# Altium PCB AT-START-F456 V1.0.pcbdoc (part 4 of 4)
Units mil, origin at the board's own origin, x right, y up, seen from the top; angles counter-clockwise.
Board outline 10942.5 x 3554 mil, 2 copper layers (Top Layer, Bottom Layer); 156 components, 201 nets, 759 pads, 796 vias.
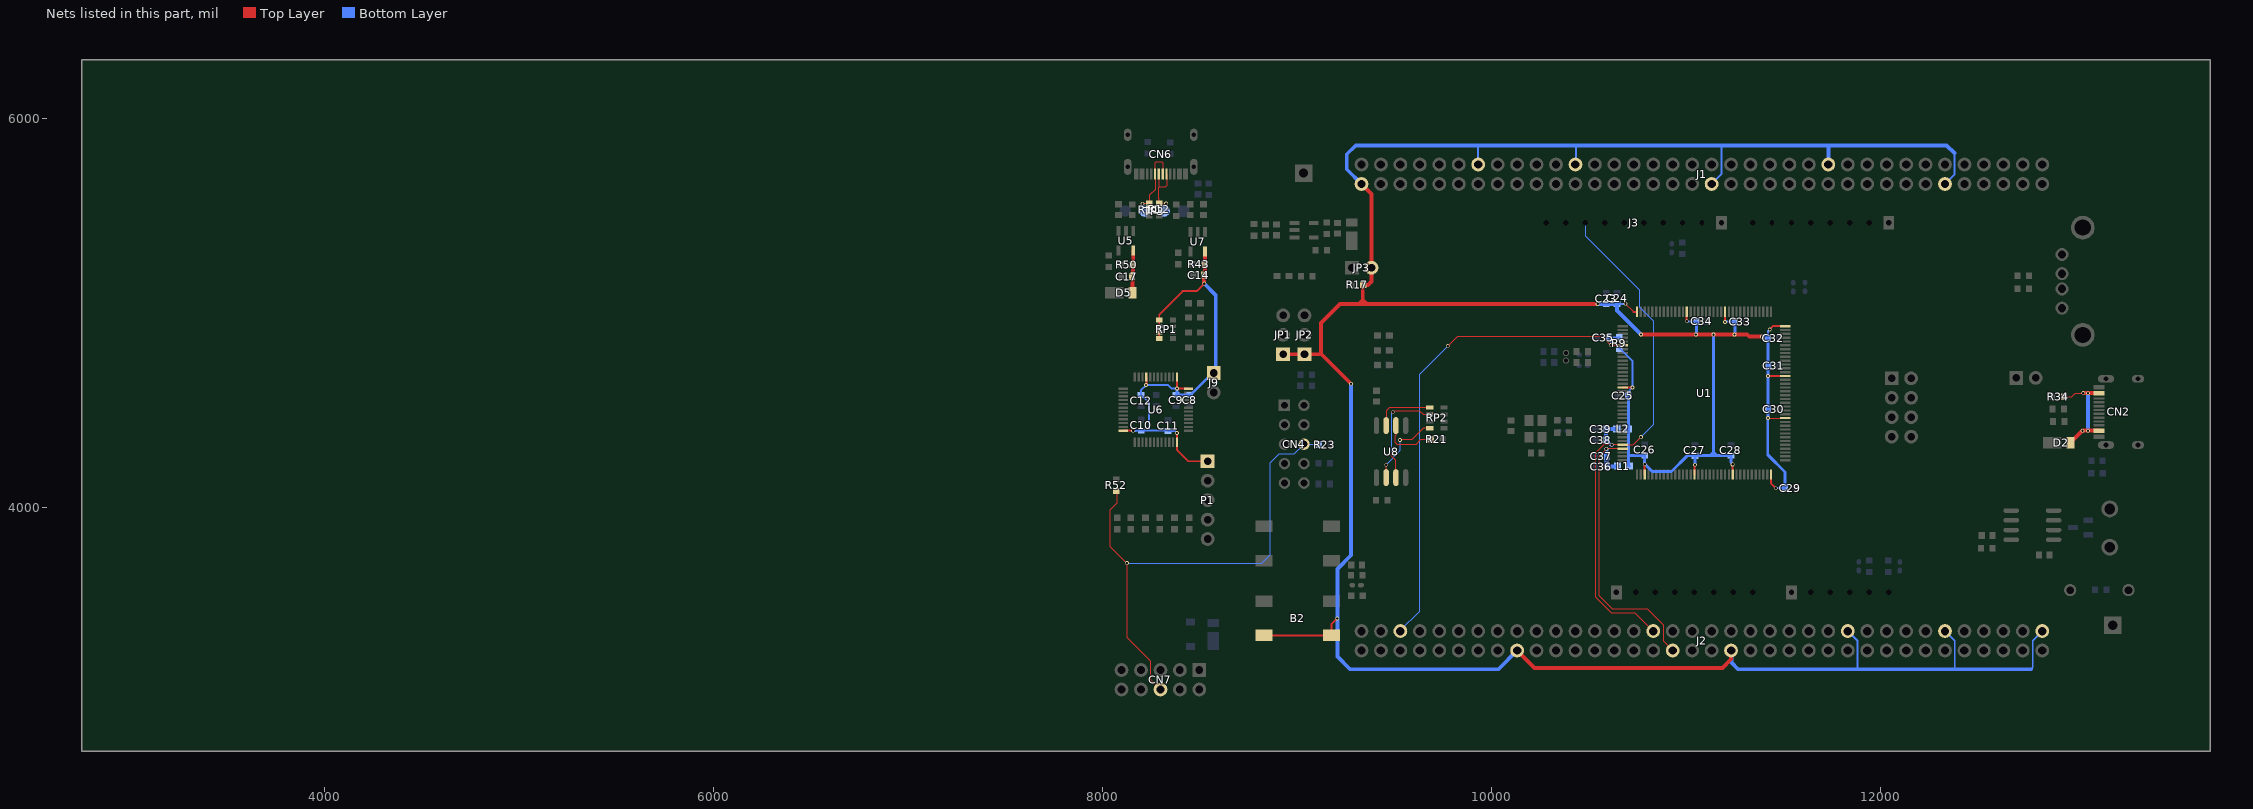
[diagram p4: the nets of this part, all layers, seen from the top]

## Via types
v1: diameter 19.7, hole 11.8, Top Layer to Bottom Layer, 419 vias
v2: diameter 19.68, hole 11.81, Top Layer to Bottom Layer, 364 vias
v3: diameter 31.5, hole 19.68, Top Layer to Bottom Layer, 12 vias
v4: diameter 27.56, hole 19.68, Top Layer to Bottom Layer, 1 vias

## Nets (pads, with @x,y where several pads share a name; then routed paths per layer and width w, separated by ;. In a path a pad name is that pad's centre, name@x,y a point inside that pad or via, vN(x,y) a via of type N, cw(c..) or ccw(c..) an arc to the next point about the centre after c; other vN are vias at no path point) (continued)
QSPI1_IO1: RP2.8 U8.2 | length 401.8
  Top Layer w5.98: U8.2@9456.16,4155.92 v2(9456.18,4222.41)
  Top Layer w6: v2(9526.59,4349.49) 9586.44,4349.49 9646.8,4409.85 RP2.8@9680.35,4409.85 ccw(c9680.11,4409.6) RP2.8@9680.11,4409.95
  Bottom Layer w6: v2(9456.18,4222.41) 9456.18,4223.22 9526.59,4293.63 v2(9526.59,4349.49)
QSPI1_IO2: RP2.6 U8.3 | length 552.2
  Top Layer w5.98: v2(9482.61,4281.14) 9482.61,4267.58 9506.16,4244.03 U8.3@9506.16,4155.92
  Top Layer w6: v2(9489.97,4492.3) 9498.29,4500.61 9625.57,4500.61 9645.47,4480.72 RP2.6@9680.35,4480.72
  Bottom Layer w5.98: v2(9482.61,4281.14) 9481.57,4282.18 9481.57,4483.9 v2(9489.97,4492.3)
QSPI1_IO3: RP2.5 U8.7 | length 307.3
  Top Layer w6: U8.7@9455.57,4424.23 ccw(c9456.18,4424.23) U8.7@9456.16,4423.64 ; U8.7@9455.56,4424.28 9455.56,4498.6 9473.1,4516.15 RP2.5@9680.35,4516.15
QSPI1_SCK: R21.2 U8.6 | length 287.1
  Top Layer w6: U8.6@9506.16,4423.64 9506.16,4374.87 9499.57,4368.29 9499.57,4340.61 9511.57,4328.61 9609.57,4328.61 9634.8,4353.85 R21.2@9685.52,4353.85
SWO: CN4.6 CN7.6 R23.1 R52.2 | length 2661.3
  Top Layer w6: 8070.23,4023.63 8035.17,3988.57 8035.17,3804.01 v2(8122.8,3716.38) 8124.77,3714.41 8124.77,3332.21 8245.21,3211.77 8245.21,3116.85 CN7.6@8295.43,3066.63 ; 8070.26,4023.68 R52.2@8070.26,4081.58
  Bottom Layer w6: v2(8122.8,3716.38) 8124.56,3714.61 8815.89,3714.61 8860.26,3758.98 8860.26,4231.98 8906.26,4277.98 8984.36,4277.98 9034.56,4328.18 9112.76,4328.18 R23.1@9112.76,4325.98
USBM: CN6.A7 CN6.B7 R12.1 TP3.2 | length 334.9
  Top Layer w6: CN6.A7@8287.41,5717.9 8287.41,5649.64 ; v2(8324.77,5565.01) 8324.24,5564.48 R12.1@8290.08,5564.48 8290.08,5586.36 8287.41,5589.03 8287.41,5649.64 ; CN6.B7@8326.71,5717.9 8326.71,5657.74 8318.61,5649.64 8287.41,5649.64
  Bottom Layer w6: TP3.2@8314.58,5526.61 8324.77,5536.8 v2(8324.77,5565.01)
USBP: CN6.A6 CN6.B6 R11.1 TP3.3 | length 398.8
  Top Layer w6: v2(8203.57,5563.81) 8203.69,5563.69 R11.1@8238.07,5563.69 8238.07,5607.32 8267.71,5636.95 CN6.B6@8267.71,5717.9 8267.71,5774.07 8272.74,5779.1 8302.29,5779.1 8307.01,5774.39 CN6.A6@8307.01,5717.9
  Bottom Layer w6: v2(8203.57,5563.81) 8203.57,5537.62 TP3.3@8214.58,5526.61
VBAT: C35.1 J2.6 R9.1 U1.6 | length 2722.4
  Top Layer w6: v2(9772.21,4831.97) 9821.36,4881.18 10566.96,4881.18 v2(10611.21,4836.97) 10612.06,4836.08 U1.6@10671.86,4836.08
  Top Layer w10: v2(10611.21,4836.97) U1.6@10671.86,4836.08
  Bottom Layer w6: J2.6@9529.17,3367.08 9529.16,3370.98 9628.26,3470.08 9628.26,4687.98 v2(9772.21,4831.97) ; C35.1@10598.77,4875.97 10654.76,4875.98 R9.1@10655.26,4875.48
  Bottom Layer w10: v2(10611.21,4836.97) 10611.16,4863.48 10598.66,4875.98 R9.1@10655.16,4875.48
VBUS: CN2.A4B9 CN2.B4A9 D2.2 R34.2 | length 552.1
  Top Layer w5.98: 12981.88,4572.61 12999.58,4590.32 v1(13039.74,4590.32)
  Top Layer w6: R34.2@12941.23,4572.61 12981.88,4572.61
  Top Layer w20: D2.2@12974.39,4335.82 v1(13035.89,4397.32) v1(13063.79,4397.32) CN2.A4B9@13120.94,4397.32 ; v1(13039.74,4590.32) CN2.B4A9@13120.94,4590.32
  Bottom Layer w20: v1(13063.79,4397.32) v1(13063.79,4589.97) v1@13064.04,4590.22
VCC: C8.2 C9.2 C10.2 C11.2 C12.2 C14.2 J9.1 P1.1 R43.1 RP1.1 RP1.2 RP1.3 RP1.4 U6.1 U6.9 U6.24 U6.36 U6.48 U7.5 | length 2489.8
  Top Layer w10: U6.24@8104.56,4397.08 8154.68,4397.08 v2(8155.18,4396.59) ; v2(8221.57,4631.81) 8222.69,4632.94 U6.9@8222.69,4672.63 ; RP1.4@8289.33,4870.97 RP1.3@8289.33,4902.46 RP1.2@8289.33,4933.96 RP1.1@8289.33,4965.45 8289.33,4994.38 8409.97,5115.01 8482.37,5115.01 v2(8520.77,5153.41) ; v2(8379.97,4385.01) 8380.17,4384.81 U6.36@8380.17,4337.98 8380.16,4298.64 8438.61,4240.18 P1.1@8538.16,4240.18 ; U6.1@8380.16,4672.68 8380.16,4632.38 8380.46,4632.08 v2(8380.46,4613.78) 8400.16,4613.78 8400.36,4613.58 U6.48@8439.26,4613.58
  Top Layer w20: v2(8520.77,5153.41) 8519.37,5154.82 C14.2@8519.37,5197.16 8524.34,5202.13 U7.5@8524.34,5318.39
  Bottom Layer w6: C10.2@8196.77,4398.65 C10.2@8198.74,4398.65
  Bottom Layer w10: v2(8155.18,4396.59) 8170.98,4396.59 8173.05,4398.65 C10.2@8196.77,4398.65 ; C10.2@8198.74,4398.65 8235.87,4398.65 ; v2(8379.97,4385.01) 8369.13,4395.85 C11.2@8335.17,4395.85 8332.01,4399.01 8299.97,4399.01 8299.61,4398.65 8235.87,4398.65 ; v2(8380.46,4613.78) 8353.6,4613.78 8335.57,4631.81 v2(8221.57,4631.81) 8196.37,4606.61 C12.2@8196.37,4579.77 8198.34,4579.77 8235.57,4542.54 8235.57,4398.95 8235.87,4398.65
  Bottom Layer w15: v2(8380.46,4613.78) 8380.46,4584.26 C9.2@8376.37,4580.17 8445.57,4580.17 C8.2@8446.37,4580.97 8450.73,4580.97 8563.33,4693.58 J9.1@8569.46,4693.58
  Bottom Layer w20: v2(8520.77,5153.41) 8579.57,5094.61 8579.57,4703.69 J9.1@8569.46,4693.58
VCC3.5V: C17.2 D5.2 R50.1 U5.5 | length 217
  Top Layer w20: D5.2@8152.36,5107.05 U5.5@8155.56,5324.05
VDD: B2.1 B2.3 C23.1 C24.1 C25.1 C26.1 C27.1 C28.1 C29.1 C30.1 C31.1 C32.1 C33.1 C34.1 J1.12 J1.23 J1.36 J1.49 J1.59 J1.72 J2.17 J2.39 J2.52 J2.62 J2.72 JP1.1 JP2.1 JP3.2 L1.1 L2.1 R9.2 R17.2 U1.17 U1.39 U1.52 U1.62 U1.72 U1.84 U1.95 U1.108 U1.121 U1.131 U1.144 | length 18180.8
  Top Layer w6: v2@10686.26,5049.98 10727.86,5008.28 ; v2(11001.21,4959.97) 11001.16,5007.88 U1.131@11001.66,5008.28 ; v2@11198.26,4955.98 11198.26,5007.98 U1.121@11198.46,5008.28 ; v2(11237.21,4223.97) 11237.86,4223.28 U1.62@11237.86,4171.68 ; v2(11419.26,4462.98) 11420.26,4461.98 11508.36,4461.98 U1.84@11508.56,4461.98
  Top Layer w10: B2.3@8828.03,3344.39 B2.1@9174.49,3344.39 9174.46,3402.18 v2@9204.26,3431.98 ; U1.17@10671.86,4619.52 v2(10722.29,4619.56) ; 10727.86,5008.28 U1.144@10745.68,5008.31 ; U1.39@10785.06,4171.68 v2(10785.09,4224.97) ; v2(11001.21,4959.97) U1.131@11001.66,5008.28 ; U1.52@11040.96,4171.68 11040.96,4218.78 v2@11044.26,4221.98 ; v2@11198.26,4955.98 U1.121@11198.46,5008.28 ; v2(11237.21,4223.97) U1.62@11237.86,4171.68 ; v2(11419.26,4678.58) U1.95@11508.48,4678.57 ; v2(11428.26,4917.98) 11444.76,4934.48 U1.108@11508.48,4934.48 ; U1.72@11434.66,4171.68 11434.66,4125.48 v2@11459.26,4100.98 ; U1.84@11508.36,4461.98 U1.84@11508.46,4462.08
  Top Layer w20: JP1.1@8926.26,4789.98 9036.26,4789.98 9121.56,4789.98 ; v2(9275.08,4638.41) 9123.56,4789.98 9121.56,4789.98 ; J1.72@9329.18,5665.65 9380.21,5614.62 JP3.2@9380.21,5234.97 ; JP3.2@9380.21,5234.97 9380.16,5164.98 9362.26,5146.98 9335.76,5146.98 9335.86,5070.28 ; J2.17@10129.17,3267.08 10218.28,3177.97 11185.21,3177.97 11229.18,3221.93 J2.39@11229.17,3267.08 ; v2@10543.26,5048.98 9357.26,5048.98 ; v2(10765.65,4891.76) 10765.87,4891.98 v2@11048.26,4891.98 ; v2(11048.21,4891.97) v2(11247.21,4891.97) 11312.67,4891.97 11323.77,4880.87 v1(11387.81,4880.87) ; 9121.56,4789.98 9121.56,4951.28 9219.26,5048.98 9315.36,5048.98 ; 9315.36,5048.98 9335.86,5070.28 ; 9315.36,5048.98 9357.26,5048.98 ; 9335.86,5070.28 9357.26,5048.98
  Bottom Layer w6: v2(11001.21,4959.97) v2@11002.16,4958.98 ; C32.1@11418.02,4872.73 C32.1@11418.02,4879.87 ; v2@11459.26,4100.98 v2@11460.26,4101.98
  Bottom Layer w10: J1.59@9929.18,5765.65 9929.18,5862.18 9931.37,5864.38 ; J1.49@10429.18,5765.65 10432.2,5768.67 10432.2,5864.38 ; C24.1@10643.21,5049.41 10685.65,5049.41 v2(10686.21,5049.97) ; R9.2@10655.16,4820.48 10658.06,4820.48 10722.26,4756.28 v2(10722.29,4619.56) 10700.76,4597.98 ; v2@11001.16,4958.98 11002.16,4958.98 C34.1@11050.76,4958.98 ; J1.36@11129.18,5665.65 11179.27,5715.74 11179.27,5864.38 ; v2@11198.26,4955.98 11200.16,4957.98 C33.1@11249.65,4957.97 ; C32.1@11419.02,4880.87 11419.02,4908.74 v2(11428.26,4917.98) ; C30.1@11420.01,4508.61 11422.36,4510.97 C30.1@11431.65,4510.97 ; v2@11459.26,4100.98 11460.16,4101.98 11460.26,4101.98 C29.1@11506.65,4101.97 ; J2.52@11829.17,3367.08 11879.21,3317.04 11879.21,3170.98 ; J2.62@12329.17,3367.08 12379.21,3317.04 12379.21,3170.98 ; J1.12@12329.18,5665.65 12377.21,5713.68 12377.21,5823.97 ; 12771.26,3170.98 12780.26,3179.98 12780.26,3318.08 J2.72@12829.17,3367.08
  Bottom Layer w15: 10700.76,4597.98 10701.87,4596.87 L2.1@10701.88,4406.61 10701.87,4270.79 10701.56,4270.48 ; L1.1@10705.57,4214.98 10701.56,4218.98 10701.56,4270.48 ; C27.1@11043.26,4268.48 11003.66,4268.48 10922.88,4187.61 10823.59,4187.61 10785.06,4226.01 10785.26,4270.48 10701.56,4270.48 ; C27.1@11043.26,4269.48 11122.36,4269.48 ; v2@11044.26,4221.98 C27.1@11044.26,4267.48 ; v2@11048.26,4891.98 11050.76,4891.98 C34.1@11050.76,4958.98 ; 11138.66,4285.98 11122.36,4269.48 ; v2(11138.7,4890.97) 11138.7,4285.98 11155.2,4269.48 ; v2@11237.26,4223.98 11228.26,4232.98 11228.26,4269.48 11155.2,4269.48 ; v2(11247.21,4891.97) 11249.66,4894.48 C33.1@11249.65,4957.97 ; v2@11418.01,4454.73 11418.01,4273.17 11420.01,4271.17 11506.65,4184.53 C29.1@11506.65,4101.97 ; v2@11420.01,4462.77 C30.1@11420.01,4508.61 C32.1@11420.01,4872.61 ; 11122.36,4269.48 11155.2,4269.48
  Bottom Layer w20: v2(9275.08,4638.41) 9275.08,3756.83 9205.26,3687.01 9205.26,3235.98 9270.26,3170.98 10033.06,3170.98 J2.17@10129.17,3267.08 ; J1.72@9329.16,5665.68 9253.46,5741.38 9253.46,5818.28 9299.56,5864.38 9931.37,5864.38 10432.2,5864.38 11179.27,5864.38 11729.18,5864.38 ; v2(10543.21,5048.97) 10587.57,5048.97 10642.77,5048.97 C24.1@10643.21,5049.41 10643.21,5014.2 v2(10765.65,4891.76) ; J2.39@11229.17,3267.08 11231.21,3265.04 11231.21,3204.97 11265.2,3170.98 11879.21,3170.98 12379.21,3170.98 12771.26,3170.98 ; v1(11387.81,4880.87) C32.1@11418.01,4880.87 ; J1.23@11729.18,5765.65 11729.18,5864.38 ; 12377.26,5823.98 12336.76,5864.38 11729.18,5864.38
  other v2: 9204.21,3431.97 11459.21,4100.97 11044.21,4221.97 11198.21,4955.97
VDDA: C36.1 C37.1 J2.33 L1.2 U1.33 | length 1590.7
  Top Layer w6: U1.33@10671.86,4304.56 10588.86,4304.58 10548.16,4263.88 10548.16,3552.03 10619.2,3480.98 10799.46,3480.98 10880.26,3400.18 10880.26,3316.08 J2.33@10929.17,3267.08
  Bottom Layer w6: v2@10588.26,4303.98 10588.66,4303.48 C37.1@10588.66,4264.98 ; L1.2@10642.86,4212.98 L1.2@10644.94,4214.98
  Bottom Layer w20: v2@10588.26,4303.98 10588.66,4264.98 10588.66,4212.98 L1.2@10642.86,4212.98 ; L1.2@10642.96,4212.98 L1.2@10644.96,4214.98
  other v2: 10588.21,4303.97
VREF+: C38.1 C39.1 J2.32 J3.8 L2.2 U1.32 | length 2915.4
  Top Layer w6: v2(10616.21,4324.97) 10671.16,4324.98 U1.32@10671.86,4324.24 ; v2@10765.66,4363.98 10725.86,4324.18 U1.32@10671.86,4324.24 ; J2.32@10829.17,3367.08 10734.26,3461.98 10612.2,3461.98 10531.56,3542.63 10531.56,4281.28 10574.46,4324.18 U1.32@10671.86,4324.24
  Bottom Layer w6: J3.8@10479.86,5465.98 10479.86,5400.33 10758.26,5121.93 10758.26,5033.65 10828.93,4962.97 10828.93,4427.25 v2@10765.66,4363.98 ; C39.1@10586.77,4404.97 10586.76,4348.98 C38.1@10587.13,4348.61 ; L2.2@10639.53,4404.98 L2.2@10641.25,4406.61
  Bottom Layer w20: v2(10616.21,4324.97) 10610.76,4324.98 C38.1@10587.13,4348.61 10587.12,4404.62 C39.1@10586.77,4404.97 L2.2@10639.53,4404.98 ; L2.2@10639.63,4404.98 L2.2@10641.27,4406.61
  other v2: 10765.63,4364
pads on no net: CN2.A8 CN2.B8 CN6.A8 CN6.B8 J4.1 J4.8 U6.2 U6.3 U6.4 U6.5 U6.6 U6.14 U6.15 U6.16 U6.17 U6.18 U6.21 U6.22 U6.29 U6.38 U6.41 U6.42 U6.43 U6.45 U6.46

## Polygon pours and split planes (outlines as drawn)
GND on Top Layer (solid, remove dead copper, pour order 0): 7929.57,6050.61 13439.57,6050.61 13439.57,3000.61 7929.57,3000.61
GND on Bottom Layer (solid, remove dead copper, pour order 2): 7904.5,6054 13442.5,6054 13442.5,3000 7904.5,3000

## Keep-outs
Top Layer:
  region: 8093.57,6044.61 8503.57,6044.61 8503.57,5692.61 8093.57,5692.61
  region: 11000.57,5092.61 11028.57,5092.61 11028.57,5089.61 11000.57,5089.61
  region: 8427.33,4456.25 8427.33,4435.51 8454.37,4435.51 8454.37,4456.25 8427.4,4456.25
  region: 9705.37,4533.67 9727.83,4533.67 9727.83,4528.15 9705.37,4528.15
Board Outline Layer:
  circle w1: c12139.81,4865.97 r62.99
  circle w10: c12139.81,4865.97 r62.99
  circle w1: c10139.81,5465.96 r62.99
  circle w10: c10139.81,5465.96 r62.99
  circle w1: c10089.81,3565.97 r62.99
  circle w10: c10089.81,3565.97 r62.99
  circle w1: c8818.39,5874.63 r62.99
  circle w10: c8818.39,5874.63 r62.99
  circle w1: c8818.39,3158.09 r62.99
  circle w10: c8818.39,3158.09 r62.99
  circle w1: c13109.73,3158.09 r62.99
  circle w10: c13109.73,3158.09 r62.99
  circle w1: c13109.73,5874.63 r62.99
  circle w10: c13109.73,5874.63 r62.99
  region: 13010.04,4104.05 13438.4,4104.05 13438.4,3683.8 13010.04,3683.8
  lines w8: 8582.96,6032.21 cw(c8582.96,5953.47) 8661.7,5953.47 8661.7,5631.63 8701.21,5631.63 8701.21,5953.46 cw(c8779.95,5953.46) 8779.95,6032.2 ; 8583.39,3000.61 ccw(c8583.39,3079.35) 8662.13,3079.35 8662.16,3079.38 8662.16,3518.58 8700.96,3518.58 8700.96,3079.38 8700.96,3079.35 ccw(c8779.7,3079.35) 8779.7,3000.61 ; 8661.66,5546.58 8661.66,5553.58 8701.26,5553.58 8701.26,5546.58 8701.22,5546.58 8701.22,5224.75 8701.22,4903.97 ; 8661.7,5546.59 8661.7,5224.75 8661.7,4904.49 ; 8661.7,4904.49 8662.57,4903.61 ; 8661.7,4904.49 ccw(c8662.57,4904.49) 8662.57,4903.61 ; 8662.57,4903.61 8700.86,4903.61 ; 8700.86,4903.61 8701.22,4903.97 ; 8700.86,4903.61 ccw(c8700.86,4903.97) 8701.22,4903.97 ; 8661.57,3606.61 8661.57,3698.61 8701.57,3698.61 8701.57,3606.61 8661.57,3606.61 ; 8661.57,3810.61 8661.57,4809.61 8661.57,4825.61 8680.57,4825.61 8700.57,4825.61 8700.57,3825.61 8700.57,3810.61 8699.57,3810.61 8661.57,3810.61
  lines w10: 7929.57,3079.35 ccw(c8008.31,3079.35) 8008.31,3000.61 13362.64,3000.61 ccw(c13362.64,3079.35) 13441.38,3079.35 13441.38,5953.37 ccw(c13362.64,5953.37) 13362.64,6032.11 8008.31,6032.11 ccw(c8008.31,5953.37) 7929.57,5953.37 7929.57,3079.35

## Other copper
Top Layer:
  drawing of 902 lines, arcs and shapes, not listed
Bottom Layer:
  drawing of 563 lines, arcs and shapes, not listed

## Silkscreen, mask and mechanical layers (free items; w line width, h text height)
Top Silkscreen Layer:
  region: 12061.06,5334.85 12023.06,5334.85 12043.06,5354.85 12063.06,5334.85
  region: 11922.7,5352.85 11960.7,5352.85 11940.7,5332.85 11920.7,5352.85
  lines w6: 8141.98,3304.61 8141.98,3603.61 ; 8238.38,3304.61 8238.38,3603.61 ; 8334.77,3303.61 8334.77,3603.61 ; 8431.17,3309.61 8431.17,3603.61
  lines w8: 8243,3218.63 8243,3258.63 8343,3258.63 8343,3217.63 ; 8533.55,3272.63 8496.55,3235.63 8457.55,3274.63 8533.55,3274.63 ; 8842.11,4558.1 8875.56,4528.18 8841.33,4499.39 8841.33,4557.7 8842.9,4557.31 ; 8881.91,4376.46 8859.05,4376.46 8859.05,4277.18 8882.06,4277.18 8882.06,4278.37
  lines w10: 10652.7,5212.76 12068.4,5212.76 ; 10942.92,3858.17 11395.93,3858.17 ; 11541.16,3858.17 12101.16,3858.17
  text "143" at 9294.03,5925.4 h53.08
  text "133" at 9778.67,5925.4 h53.08
  text "123" at 10283.4,5925.34 h53.08
  text "113" at 10800.72,5925.42 h53.08
  text "103" at 11286.94,5925.43 h53.08
  text "93" at 11797.25,5925.41 h53.08
  text "83" at 12303.16,5925.43 h53.08
  text "73" at 12798.04,5925.41 h53.08
  text "D8" at 12614.84,5826.64 h53.08 r45
  text "B12" at 12814.13,5827.4 h53.08 r45
  text "E0" at 9430.12,5824.52 h53.08 r45
  text "D7" at 10318.9,5825.28 h53.08 r45
  text "D12" at 12415.09,5824.62 h53.08 r45
  text "D10" at 12514.89,5825.31 h53.08 r45
  text "B14" at 12714.99,5825.34 h53.08 r45
  text "B8" at 9526.51,5823.55 h53.08 r45
  text "B3" at 9826.63,5823.87 h53.08 r45
  text "D1" at 10725.32,5823.89 h53.08 r45
  text "A14" at 11016.9,5823.66 h53.08 r45
  text "A13" at 11214.65,5823.89 h53.08 r45
  text "A11*" at 11319.48,5823.92 h53.08 r45
  text "A9" at 11426.06,5823.63 h53.08 r45
  text "D14" at 12219.86,5823.66 h53.08 r45
  text "B5" at 9727.99,5823.17 h53.08 r45
  text "D5" at 10530.89,5822.21 h53.08 r45
  text "D3" at 10626.84,5822.42 h53.08 r45
  text "B7" at 9625.2,5820.13 h53.08 r45
  text "G10" at 10218.23,5820.36 h53.08 r45
  text "G8" at 11820.07,5819.93 h53.08 r45
  text "G12" at 10118.32,5818.91 h53.08 r45
  text "GND" at 11114.44,5819.33 h53.08 r45
  text "G2" at 12119.89,5819.18 h53.08 r45
  text "GND" at 9334.9,5817.96 h53.08 r45
  text "C7" at 11625.79,5817.66 h53.08 r45
  text "G6" at 11922.73,5818.3 h53.08 r45
  text "C12" at 10818.19,5816.54 h53.08 r45
  text "C9" at 11519.64,5817.36 h53.08 r45
  text "G4" at 12017.33,5817.43 h53.08 r45
  text "GND" at 12312.34,5817.24 h53.08 r45
  text "G14" at 10017.34,5816.49 h53.08 r45
  text "VDD" at 10418.16,5815.77 h53.08 r45
  text "C10" at 10920.36,5815.82 h53.08 r45
  text "VDD" at 11710.07,5815.74 h53.08 r45
  text "VDD" at 9913.84,5812.5 h53.08 r45
  text "GND" at 8977.64,5808.6 h61.93
  text "B6" at 9742.77,5537.36 h53.08 r45
  text "B9" at 9540.12,5533.83 h53.08 r45
  text "E1" at 9435.76,5530.95 h53.08 r45
  text "B4" at 9835.99,5531.15 h53.08 r45
  text "D6" at 10432.23,5530.95 h53.08 r45
  text "G11" at 10230.83,5527.56 h53.08 r45
  text "D4" at 10637.55,5524.86 h53.08 r45
  text "G13" at 10109.58,5524.31 h53.08 r30
  text "G9" at 10324.42,5524.4 h53.08 r45
  text "D0" at 10838.83,5524.06 h53.08 r45
  text "G5" at 12031.09,5523.75 h53.08 r45
  text "G3" at 12133.79,5523.58 h53.08 r45
  text "D2" at 10739.23,5522.71 h53.08 r45
  text "H2" at 11232.67,5523.43 h53.08 r45
  text "C6" at 11737.72,5522.99 h53.08 r45
  text "G7" at 11932.92,5522.76 h53.08 r45
  text "A8" at 11533.03,5521.69 h53.08 r45
  text "C8" at 11633,5522.25 h53.08 r45
  text "C11" at 10934.3,5519.65 h53.08 r45
  text "A10" at 11429.72,5519.73 h53.08 r45
  text "G15" at 9928.83,5517.95 h53.08 r45
  text "D11" at 12532.33,5516.61 h53.08 r45
  text "A15" at 11025.3,5515.46 h53.08 r45
  text "D15" at 12226.07,5515 h53.08 r45
  text "D9" at 12634.99,5513.64 h53.08 r45
  text "VDD" at 9317.08,5512.52 h53.08 r45
  text "GND" at 11820.45,5513.47 h53.08 r45
  text "GND" at 10021.29,5511.87 h53.08 r45
  text "GND" at 10526.54,5511.97 h53.08 r45
  text "A12*" at 11322.84,5511.95 h53.08 r45
  text "B15" at 12734.91,5511.09 h53.08 r45
  text "D13" at 12427.78,5509.01 h53.08 r45
  text "B13" at 12832.59,5509.41 h53.08 r45
  text "VDD" at 11121.07,5507.7 h53.08 r45
  text "VDD" at 12323.24,5503.68 h53.08 r45
  text "BOOT0" at 9597.79,5485.43 h44.24 r45
  text "HOST" at 13163.09,5483.02 h80
  text "4" at 11676.82,5362.91 h69.7 r90
  text "8" at 11216.74,5361.97 h69.7 r90
  text "7" at 11379.82,5361.91 h69.7 r90
  text "2" at 11873.82,5361.91 h69.7 r90
  text "13" at 10719.33,5322.2 h70.78 r90
  text "12" at 10819.33,5322.2 h70.78 r90
  text "#6" at 11476.41,5316.14 h70.78 r90
  text "#5" at 11577.41,5316.14 h70.78 r90
  text "#9" at 11120.33,5315.2 h70.78 r90
  text "#3" at 11776.41,5315.14 h70.78 r90
  text "#11" at 10920.62,5295.36 h70.78 r90
  text "#10" at 11019.98,5289.01 h70.78 r90
  text "GND" at 10621.15,5268.8 h70.78 r90
  text "SCL" at 10315.33,5266.66 h70.78 r90
  text "SDA" at 10415.33,5266.66 h70.78 r90
  text "RX 0" at 12081.98,5235.78 h70.78 r90
  text "TX 1" at 11978.75,5234.59 h70.78 r90
  text "DIGITAL(#=PWM)" at 11091.16,5233.28 h61.93
  text "AREF" at 10519.33,5230.13 h70.78 r90
  text "IDD" at 9470.36,5181.95 h88.47
  text "LD:" at 8563.5,5173.13 h72 r270
  text "1" at 8564.8,5059.26 h72 r270
  text "BOOT0" at 8780.66,5046.26 h61.93
  text "BOOT1" at 9002.5,5046.34 h61.93
  text "AT-Link-EZ V1.4" at 7962.83,5043.28 h88.47 r270
  text "2" at 8564.01,4994.65 h72 r270
  text "GND" at 9102.99,4961.2 h61.93
  text "GND" at 8752.93,4958.23 h61.93
  text "3" at 8562.83,4916.24 h72 r270
  text "4" at 8563.62,4842.17 h72 r270
  text "VDD" at 9107.84,4761.9 h53.08
  text "VDD" at 8764.81,4752.09 h53.08
  text "PA9" at 12618.57,4739.61 h61.93
  text "VBUS" at 12761.57,4739.61 h61.93
  text "DEVICE" at 13140.45,4713.3 h82.58
  text "MISO" at 11855.88,4637.16 h61.93
  text "5V" at 12243.86,4635.19 h61.93
  text "MOSI" at 12227.93,4534.8 h61.93
  text "SCK" at 11869.55,4528.11 h61.93
  text "5V" at 9142.77,4499.98 h61.93
  text "3V3" at 8717.21,4492.94 h61.93
  text "NRST" at 11850.76,4434.8 h61.93
  text "GND" at 12225.46,4428.9 h61.93
  text "BOOT0" at 9120.67,4404.83 h60
  text "SWD" at 8723.91,4396.56 h61.93
  text "NSS" at 11871.52,4335.19 h61.93
  text "PB11" at 12230.68,4330.47 h61.93
  text "SWO" at 9124.61,4298.84 h61.93
  text "SWC" at 8720.95,4293.48 h61.93
  text "TX" at 9147.1,4197.39 h61.93
  text "NRST" at 8726.32,4195.36 h61.93
  text "CAN1" at 13153.57,4127.61 h82.58
  text "GND" at 8729.57,4094.61 h61.93
  text "RX" at 9151.43,4089.04 h61.93
  text "AT-Link" at 8853.71,3980.2 h82.58
  text "H" at 13424.57,3961.61 h80 r90
  text "AT-START-F456 V1.0" at 11162.69,3874.31 h120
  text "L" at 13419.57,3783.61 h80 r90
  text "POWER" at 11194.49,3781.08 h61.93
  text "ANALOG IN" at 11702.36,3781.07 h61.93
  text "IOREF" at 10781.5,3653.97 h70.78 r90
  text "RESET" at 10876.33,3653.59 h70.78 r90
  text "3.3V" at 10977.33,3651.13 h70.78 r90
  text "GND" at 11178.33,3649.66 h70.78 r90
  text "GND" at 11277.62,3649.66 h70.78 r90
  text "5V" at 11077.33,3648.2 h70.78 r90
  text "AN0" at 11575.41,3646.71 h70.78 r90
  text "AN1" at 11672.34,3646.71 h70.78 r90
  text "AN3" at 11873.28,3644.74 h70.78 r90
  text "AN5" at 12077.37,3644.74 h70.78 r90
  text "AN2" at 11775.17,3643.55 h70.78 r90
  text "AN4" at 11977.29,3643.55 h70.78 r90
  text "3V3" at 8437.43,3599.5 h61.93 r270
  text "RESET" at 8892.74,3598.53 h82.58
  text "SWD" at 8348.38,3597.53 h61.93 r270
  text "SWC" at 8249.49,3594.38 h61.93 r270
  text "GND" at 8063.35,3592.36 h61.93 r270
  text "NRST" at 8151.38,3591.91 h61.93 r270
  text "120Ω" at 13423.57,3478.61 h80 r90
  text "F0" at 9717.75,3430.69 h53.08 r45
  text "A2" at 11016.8,3430.92 h53.08 r45
  text "E11" at 12421.2,3431.34 h53.08 r45
  text "E15" at 12625.13,3429.59 h53.08 r45
  text "BOOT0" at 8348.38,3429.49 h61.93 r270
  text "A0" at 10918.4,3429 h53.08 r45
  text "E13" at 12513.82,3428.86 h53.08 r45
  text "F2" at 9822.53,3428.08 h53.08 r45
  text "A4" at 11221.98,3428.26 h53.08 r45
  text "E9" at 12229.37,3428.26 h53.08 r45
  text "SWO" at 8252.64,3426.93 h61.93 r270
  text "E3" at 9317.76,3427.09 h53.08 r45
  text "F4" at 9922.58,3426.55 h53.08 r45
  text "B0" at 11519.56,3426.9 h53.08 r45
  text "F6" at 10118.12,3425.55 h53.08 r45
  text "H1*" at 10420.77,3425.87 h53.08 r45
  text "E5" at 9426.43,3424.75 h53.08 r45
  text "H4" at 10718.04,3425.31 h53.08 r45
  text "B2" at 11620.73,3425.34 h53.08 r45
  text "F12" at 11719.48,3425.46 h53.08 r45
  text "F14" at 11920.05,3424.78 h53.08 r45
  text "B11" at 12722.85,3425.28 h53.08 r45
  text "F10" at 10317.32,3423.73 h53.08 r45
  text "A6" at 11315.47,3424.27 h53.08 r45
  text "E7" at 12126.2,3424.38 h53.08 r45
  text "F8" at 10221.06,3423.09 h53.08 r45
  text "C2" at 10617.79,3423.01 h53.08 r45
  text "G0" at 12024.4,3422.35 h53.08 r45
  text "C0" at 10516.48,3420.09 h53.08 r45
  text "C4" at 11415.99,3420.01 h53.08 r45
  text "VDD" at 12308.18,3419.91 h53.08 r45
  text "C14*" at 9609.03,3418.94 h53.08 r45
  text "VREF+" at 10776.53,3417.68 h44.24 r30
  text "VDD" at 11807.47,3417.75 h53.08 r45
  text "VDD" at 12810.73,3418.26 h53.08 r45
  text "VBAT" at 9504.82,3417.02 h53.08 r45
  text "GND" at 11114.96,3417.09 h53.08 r45
  text "GND" at 9999.65,3416.16 h53.08 r30
  text "TX" at 8155.32,3409.69 h61.93 r270
  text "5V" at 8436.64,3406.14 h61.93 r270
  text "RX" at 8062.34,3405.35 h61.93 r270
  text "GND" at 13289.57,3359.61 h61.93
  text "USER" at 8908.71,3214.28 h82.58
  text "C1" at 10637.03,3136.76 h53.08 r45
  text "B1" at 11635.5,3133.71 h53.08 r45
  text "G1" at 12137.35,3134.24 h53.08 r45
  text "F5" at 10038.42,3132.15 h53.08 r45
  text "C3" at 10736.94,3132.35 h53.08 r45
  text "F1" at 9841.47,3131.1 h53.08 r45
  text "A5" at 11338.4,3130.12 h53.08 r45
  text "F3" at 9936.58,3128.84 h53.08 r45
  text "E2" at 9335.59,3128.23 h53.08 r45
  text "F9" at 10341.35,3128.11 h53.08 r45
  text "A3" at 11133.89,3128.19 h53.08 r45
  text "C5" at 11536.52,3128.27 h53.08 r45
  text "F11" at 11734.83,3127.56 h53.08 r45
  text "E8" at 12230.09,3128.26 h53.08 r45
  text "A1" at 11037.09,3127.48 h53.08 r45
  text "A7" at 11433.35,3126.7 h53.08 r45
  text "E6" at 9537.6,3126.18 h53.08 r45
  text "E4" at 9431.84,3125.38 h53.08 r45
  text "F7" at 10243.95,3124.35 h53.08 r45
  text "H0*" at 10427.81,3122.94 h53.08 r45
  text "E12" at 12534.33,3122.98 h53.08 r45
  text "H3" at 12838.3,3122.46 h53.08 r45
  text "F13" at 11935.66,3120.69 h53.08 r45
  text "F15" at 12034.14,3120.52 h53.08 r45
  text "E10" at 12438.37,3120.36 h53.08 r45
  text "E14" at 12639.85,3120.08 h53.08 r45
  text "B10" at 12732.23,3120.34 h53.08 r45
  text "C13" at 9633.25,3116.92 h53.08 r45
  text "GND" at 11820.04,3114.32 h53.08 r45
  text "VDD" at 10122.81,3111.97 h53.08 r45
  text "GND" at 10820.45,3112.48 h53.08 r45
  text "VDD" at 11222.75,3108.88 h53.08 r45
  text "GND" at 12321.19,3109.27 h53.08 r45
  text "C15*" at 9724.16,3107.16 h53.08 r45
  text "NRST" at 10521.19,3084.69 h53.08 r45
  text "VDDA" at 10908.51,3083.8 h53.08 r45
  text "1" at 9317.99,3057.82 h52.27
  text "11" at 9823.24,3057.36 h53.08
  text "21" at 10313.01,3057.33 h53.08
  text "31" at 10811.82,3057.33 h53.08
  text "41" at 11307.49,3057.3 h53.08
  text "51" at 11803.16,3057.31 h53.08
  text "61" at 12308.67,3057.31 h53.08
  text "71" at 12819.69,3057.36 h53.08
Bottom Silkscreen Layer:
  text "143" at 9380.01,5855.94 h53.08 r45
  text "139" at 9572.01,5854.79 h53.08 r45
  text "135" at 9788.01,5855.36 h53.08 r45
  text "133" at 9892.01,5855.36 h53.08 r45
  text "129" at 10077.34,5854.79 h53.08 r45
  text "125" at 10280.27,5855.36 h53.08 r45
  text "123" at 10380.27,5855.36 h53.08 r45
  text "109" at 11076.34,5854.79 h53.08 r45
  text "105" at 11285.09,5855.36 h53.08 r45
  text "103" at 11377.86,5855.36 h53.08 r45
  text "141" at 9470.68,5853.05 h53.08 r45
  text "137" at 9681.34,5851.89 h53.08 r45
  text "131" at 9985.34,5852.47 h53.08 r45
  text "127" at 10174.68,5851.89 h53.08 r45
  text "121" at 10477.6,5852.47 h53.08 r45
  text "107" at 11178.09,5851.89 h53.08 r45
  text "101" at 11462.19,5852.47 h53.08 r45
  text "119" at 10573.6,5849.58 h53.08 r45
  text "115" at 10774.94,5850.16 h53.08 r45
  text "113" at 10879.34,5850.16 h53.08 r45
  text "95" at 11766.34,5848.85 h53.08 r45
  text "93" at 11868.48,5848.85 h53.08 r45
  text "85" at 12261.98,5848.85 h53.08 r45
  text "83" at 12369.39,5848.85 h53.08 r45
  text "99" at 11564.48,5848.28 h53.08 r45
  text "89" at 12065.53,5848.28 h53.08 r45
  text "117" at 10674.94,5846.69 h53.08 r45
  text "111" at 10967.34,5847.26 h53.08 r45
  text "79" at 12565.52,5846.54 h53.08 r45
  text "75" at 12767.44,5847.12 h53.08 r45
  text "73" at 12867.15,5847.12 h53.08 r45
  text "91" at 11959.39,5845.96 h53.08 r45
  text "81" at 12466.24,5845.96 h53.08 r45
  text "97" at 11660.48,5845.38 h53.08 r45
  text "87" at 12163.91,5845.38 h53.08 r45
  text "77" at 12665.72,5843.65 h53.08 r45
  text "142" at 9474.68,5579.59 h53.08 r45
  text "132" at 9978.68,5579.01 h53.08 r45
  text "122" at 10468.27,5579.01 h53.08 r45
  text "102" at 11480.29,5579.01 h53.08 r45
  text "144" at 9369.93,5577.28 h53.08 r45
  text "140" at 9576.01,5577.28 h53.08 r45
  text "138" at 9677.34,5577.28 h53.08 r45
  text "134" at 9881.34,5576.7 h53.08 r45
  text "130" at 10070.68,5576.7 h53.08 r45
  text "128" at 10176.01,5577.28 h53.08 r45
  text "124" at 10373.6,5576.7 h53.08 r45
  text "120" at 10580.27,5576.7 h53.08 r45
  text "108" at 11175.34,5577.28 h53.08 r45
  text "104" at 11373.53,5576.7 h53.08 r45
  text "100" at 11574.86,5576.7 h53.08 r45
  text "136" at 9785.34,5576.12 h53.08 r45
  text "126" at 10276.27,5576.12 h53.08 r45
  text "106" at 11265.09,5576.12 h53.08 r45
  text "112" at 10967.01,5573.81 h53.08 r45
  text "118" at 10672.27,5572.07 h53.08 r45
  text "92" at 11965.2,5572.5 h53.08 r45
  text "82" at 12469.15,5572.5 h53.08 r45
  text "116" at 10764.27,5570.91 h53.08 r45
  text "114" at 10867.01,5571.49 h53.08 r45
  text "110" at 11067.34,5571.49 h53.08 r45
  text "98" at 11671.3,5570.77 h53.08 r45
  text "88" at 12172.96,5570.77 h53.08 r45
  text "96" at 11769.96,5569.61 h53.08 r45
  text "94" at 11868.63,5570.19 h53.08 r45
  text "90" at 12071.53,5570.19 h53.08 r45
  text "86" at 12266.87,5569.61 h53.08 r45
  text "84" at 12368.53,5570.19 h53.08 r45
  text "80" at 12571.11,5570.19 h53.08 r45
  text "78" at 12671.73,5569.03 h53.08 r45
  text "76" at 12773.3,5567.87 h53.08 r45
  text "74" at 12873.87,5568.45 h53.08 r45
  text "VDD" at 8473.57,4642.61 h53.08 r270
  text "GND" at 8485.57,3808.61 h53.08
  text "AT32F456ZET7" at 11707.59,3757.38 h232.22
  text "42" at 11372.69,3453.66 h53.08 r45
  text "48" at 11673.41,3451.92 h53.08 r45
  text "40" at 11274.46,3451.34 h53.08 r45
  text "44" at 11469.84,3451.35 h53.08 r45
  text "46" at 11573.41,3450.77 h53.08 r45
  text "22" at 10368.8,3449.61 h53.08 r45
  text "62" at 12371.46,3449.03 h53.08 r45
  text "28" at 10669.28,3447.87 h53.08 r45
  text "32" at 10868.2,3448.45 h53.08 r45
  text "52" at 11870.12,3448.45 h53.08 r45
  text "20" at 10266.44,3447.3 h53.08 r45
  text "24" at 10469.59,3447.29 h53.08 r45
  text "26" at 10566.42,3446.72 h53.08 r45
  text "38" at 11173.03,3446.72 h53.08 r45
  text "58" at 12171.46,3446.72 h53.08 r45
  text "60" at 12270.46,3446.72 h53.08 r45
  text "64" at 12467.79,3446.72 h53.08 r45
  text "68" at 12666.79,3447.29 h53.08 r45
  text "72" at 12867.79,3447.3 h53.08 r45
  text "30" at 10770.34,3446.14 h53.08 r45
  text "34" at 10971.05,3446.14 h53.08 r45
  text "36" at 11070.17,3445.56 h53.08 r45
  text "50" at 11769.69,3446.14 h53.08 r45
  text "54" at 11973.12,3446.14 h53.08 r45
  text "56" at 12071.12,3445.56 h53.08 r45
  text "66" at 12566.79,3446.14 h53.08 r45
  text "70" at 12767.79,3444.98 h53.08 r45
  text "12" at 9860.93,3444.4 h53.08 r45
  text "18" at 10163.68,3442.67 h53.08 r45
  text "10" at 9760.53,3442.09 h53.08 r45
  text "14" at 9960.14,3442.09 h53.08 r45
  text "16" at 10058.56,3441.51 h53.08 r45
  text "4" at 9454.18,3439.81 h52.27 r45
  text "2" at 9353,3438.65 h52.27 r45
  text "6" at 9553.39,3435.76 h52.27 r45
  text "8" at 9655.36,3436.34 h52.27 r45
  text "43" at 11471.07,3178.79 h53.08 r45
  text "45" at 11568.21,3178.79 h53.08 r45
  text "49" at 11771.64,3178.21 h53.08 r45
  text "41" at 11365.35,3175.9 h53.08 r45
  text "23" at 10469.93,3174.74 h53.08 r45
  text "25" at 10569.08,3174.74 h53.08 r45
  text "47" at 11671.07,3175.32 h53.08 r45
  text "29" at 10766.57,3174.16 h53.08 r45
  text "33" at 10967.29,3173.58 h53.08 r45
  text "35" at 11069.12,3173.58 h53.08 r45
  text "53" at 11971.78,3173.58 h53.08 r45
  text "55" at 12067.78,3173.58 h53.08 r45
  text "63" at 12469.45,3174.16 h53.08 r45
  text "65" at 12576.45,3174.16 h53.08 r45
  text "69" at 12769.45,3173.58 h53.08 r45
  text "39" at 11272.12,3173 h53.08 r45
  text "59" at 12269.12,3173 h53.08 r45
  text "21" at 10363.71,3171.85 h53.08 r45
  text "27" at 10672.65,3171.27 h53.08 r45
  text "31" at 10863.71,3170.69 h53.08 r45
  text "51" at 11861.78,3170.69 h53.08 r45
  text "61" at 12366.12,3171.27 h53.08 r45
  text "67" at 12672.45,3170.69 h53.08 r45
  text "13" at 9961.34,3169.53 h53.08 r45
  text "15" at 10068.69,3169.53 h53.08 r45
  text "37" at 11167.83,3170.11 h53.08 r45
  text "57" at 12168.12,3170.11 h53.08 r45
  text "71" at 12864.45,3169.53 h53.08 r45
  text "19" at 10261.81,3168.96 h53.08 r45
  text "11" at 9858.98,3166.64 h53.08 r45
  text "17" at 10164.84,3166.06 h53.08 r45
  text "3" at 9457.35,3162.63 h52.27 r45
  text "5" at 9554.6,3162.63 h52.27 r45
  text "9" at 9752.63,3163.2 h52.27 r45
  text "1" at 9347.12,3160.89 h52.27 r45
  text "7" at 9655.39,3158 h52.27 r45
Mechanical Layer:
  circle w1: c12139.81,4865.97 r62.99
  circle w1: c10139.81,5465.96 r62.99
  circle w1: c10089.81,3565.97 r62.99
  circle w1: c8818.39,5874.63 r62.99
  circle w1: c8818.39,3158.09 r62.99
  circle w1: c13109.73,3158.09 r62.99
  circle w1: c13109.73,5874.63 r62.99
